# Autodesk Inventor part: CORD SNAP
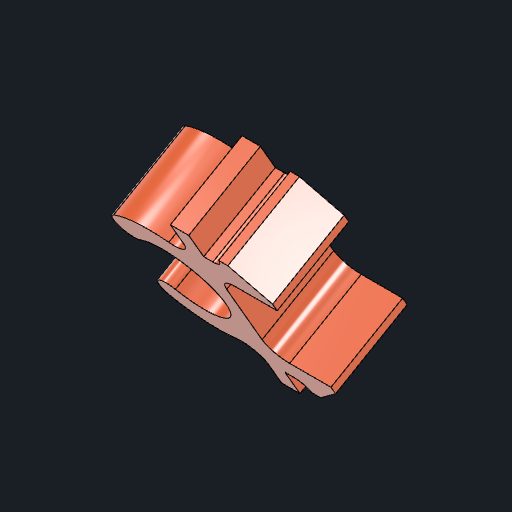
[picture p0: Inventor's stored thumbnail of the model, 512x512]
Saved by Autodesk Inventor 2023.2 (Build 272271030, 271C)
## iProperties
Created: 2022-12
Part Number: CORD SNAP
Material: Generic
Document SubType Name: Modeling
Designer: AR
Mass: 1.41045 g
Surface Area: 12.9784 cm^2
Volume: 1.41045 cm^3
Density: 1 g/cm^3
Appearance: Smooth - Light Orange
Author: AR
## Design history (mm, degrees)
derived "_2 SPOOL CORD WRAP MP.ipt"
  sketch "CORD GRIP PROFILE SKT 1"
    geometry: L1 (2, 5.839)-(2, -1.219) reference; L2 (0, -1.219)-(0, 10.819) reference; L3 (7, -9.1)-(75, -9.1) reference; L4 (0, 3)-(-2, 3) reference; L5 (-2, 3)-(-2, -9.1) reference; L6 (-2, -9.1)-(0, -9.1) reference; L7 (0, -9.1)-(0, 3) reference; L8 (6.5, -3.25)-(0, -3.25) reference; L9 (1, -0.25)-(0, -0.25) reference; L10 (2.25, 1)-(3.25, 1) reference; L11 (3.25, 1)-(6.5, -2.25) reference; L12 (6.5, -2.25)-(6.5, -3.25) reference; L13 (-2, -5.1)-(-11.433, -5.1) reference; L14 (-12.933, -5.1)-(-12.933, -0.34) reference; A1 r 1.25 centre (1, 1) between (1, -0.25) and (2.25, 1) reference; A2 r 5.35 centre (-7.35, -9.1) between (-2, -9.1) and (-10.539, -4.804) reference; A3 r 1.5 centre (-11.433, -3.6) between (-12.327, -2.396) and (-10.539, -4.804) reference; A4 r 8.35 centre (-7.35, -9.1) between (-2, -2.689) and (-12.327, -2.396) reference; 2 further points
  node "CORD GRIP PROFILE WPL 1"
workplane "Work Plane1"
sketch "Sketch2"
  geometry: L1 (-2, 3)-(-2, -9.1) reference; L2 (-2, -5.1)-(-11.433, -5.1) reference; L3 (-12.933, -5.1)-(-12.933, -0.34) reference; L4 (-6.65, -9.1)-(-2, -9.1); L5 (-2, -5.623)-(-11.763, -5.623); L6 (-11.763, -5.623)-(-11.763, -1.663); L7 (-2, -3.025)-(-2, -15.175); A1 r 5.35 centre (-7.35, -9.1) between (-2, -9.1) and (-10.539, -4.804) reference; A2 r 1.5 centre (-11.433, -3.6) between (-12.327, -2.396) and (-10.539, -4.804) reference; A3 r 8.35 centre (-7.35, -9.1) between (-2, -2.689) and (-12.327, -2.396) reference; A4 r 4.65 centre (-6.65, -9.1) between (-9.382, -12.863) and (-9.382, -5.337); A5 r 7.65 centre (-6.65, -9.1) between (-11.145, -15.29) and (-11.145, -2.91); A6 r 1.5 centre (-10.263, -4.123) between (-11.145, -2.91) and (-9.382, -5.337); A7 r 1.5 centre (-10.263, -14.077) between (-9.382, -12.863) and (-11.145, -15.29); 2 further points
  constraints: 10 point on circle, 8 end point, 7 tangent, 4 centre point, 3 point on line, 2 perpendicular, 1 horizontal, 1 symmetric about line
  dimensions: "d2" = 9.3 diameter of A4; "d3" = 3 radial gap between concentric circles of A4 A5; "d4" = 10.7 diameter of A1 (derived); "d5" = 8 diameter of L2 L4 (derived); "d6" = 6.95327 diameter of L5 L4 (computed from d4, d5, d2); "d13" = 7.65 radius of A5 (derived)
split "Split1"
extrude "Extrusion1" join sketch "Sketch2" stored distance "d7" = 9; taper "d8" = 0 deg
fillet "Fillet1" dims "d9" = 2
node "Direct Edit1"
pattern_circular "Circular Pattern1" dims "d15" = 360 deg
fillet "Fillet2" dims "d17" = 2
fillet "Fillet3" dims "d18" = 1
feature "CORD SNAP::_2 SPOOL CORD WRAP MP.ipt" dims "d0" = 10
tag "TaggingFeature1"
node "CORD SNAP"
move_body "Move1" dims "d12" = 8
other parameters: "d10" = 0, "d11" = 0
